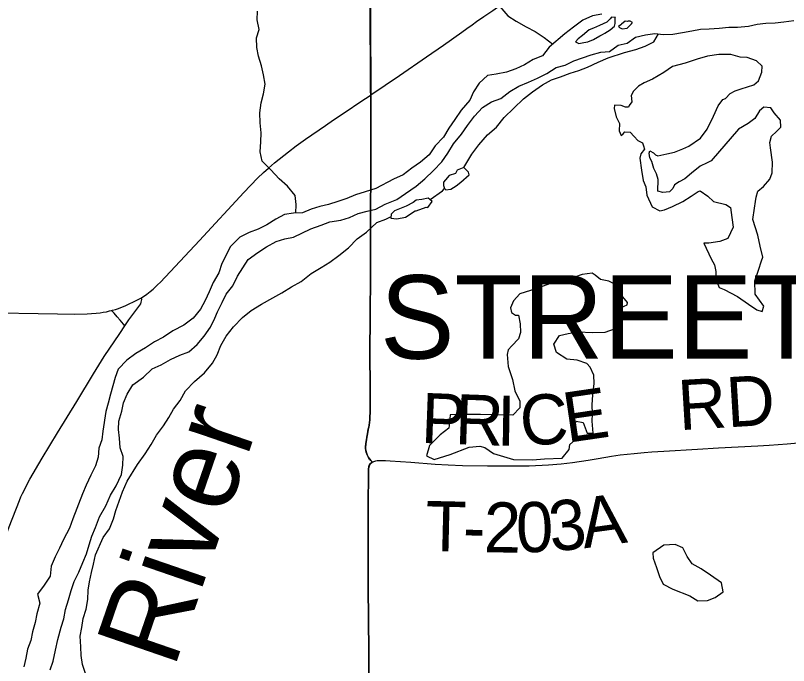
# Model space of a CAD drawing. Extents: x 0 to 34, y 0 to 22.
# Drawn here: x 4.634 to 5.511, y 19.311 to 20.048 of the extents above; entities that cross this region are included whole.
import ezdxf

# ---------------------------------------------------------------- set-up
doc = ezdxf.new("R2010")
doc.units = 0
for name, color, linetype in [('GM_X_Corporation', 7, 'Continuous'), ('GM_X_Corporation_Text', 7, 'Continuous'), ('GM_X_County_Road', 7, 'Continuous'), ('GM_X_Major_River', 7, 'Continuous'), ('GM_X_Major_River_Text', 7, 'Continuous'), ('GM_X_Minor_Lake', 7, 'Continuous'), ('GM_X_Minor_River', 7, 'Continuous'), ('GM_X_State_Route', 7, 'Continuous'), ('GM_X_Township_Road', 7, 'Continuous'), ('GM_X_Township_Road_Text', 7, 'Continuous')]:
    doc.layers.add(name, color=color, linetype=linetype)

msp = doc.modelspace()

# ---------------------------------------------------------------- linework, layer by layer
at = {"layer": 'GM_X_Corporation'}
for points in [[(5.03504, 19.29275), (5.03495, 19.3162), (5.0349, 19.32692), (5.03433, 19.39965), (5.03427, 19.41918), (5.03421, 19.43789), (5.03417, 19.48319), (5.03427, 19.50106), (5.03438, 19.52093), (5.03445, 19.52986), (5.03454, 19.5329), (5.03461, 19.5345), (5.03475, 19.53565), (5.03496, 19.53682), (5.03539, 19.53813), (5.0358, 19.539), (5.03614, 19.53952), (5.03672, 19.54018), (5.03742, 19.54089), (5.03811, 19.54154), (5.03872, 19.54193), (5.03731, 19.54354), (5.03559, 19.54551), (5.0347, 19.54673), (5.03384, 19.54824), (5.03316, 19.54973), (5.03268, 19.55096), (5.03187, 19.55339), (5.03142, 19.55502), (5.03126, 19.5567), (5.03122, 19.55786), (5.03129, 19.55916), (5.03155, 19.56216), (5.03187, 19.56508), (5.03212, 19.567), (5.03256, 19.56981), (5.0333, 19.57381), (5.03431, 19.57896), (5.03483, 19.5814), (5.03521, 19.5835), (5.03562, 19.58658), (5.03594, 19.58942), (5.03611, 19.59283), (5.03627, 19.5977), (5.03644, 19.6042), (5.03636, 19.61029), (5.03627, 19.63203), (5.03622, 19.65931), (5.03624, 19.67067), (5.03631, 19.70152), (5.03632, 19.71072), (5.03638, 19.71754), (5.03656, 19.72566), (5.03667, 19.73551), (5.03701, 19.95856), (5.037, 19.96155), (5.03541, 20.38763)], [(5.03504, 19.29275), (5.03495, 19.3162), (5.0349, 19.32692), (5.03433, 19.39965), (5.03427, 19.41918), (5.03421, 19.43789), (5.03417, 19.48319), (5.03427, 19.50106), (5.03438, 19.52093), (5.03445, 19.52986), (5.03454, 19.5329), (5.03461, 19.5345), (5.03475, 19.53565), (5.03496, 19.53682), (5.03539, 19.53813), (5.0358, 19.539), (5.03614, 19.53952), (5.03672, 19.54018), (5.03742, 19.54089), (5.03811, 19.54154), (5.03872, 19.54193), (5.03731, 19.54354), (5.03559, 19.54551), (5.0347, 19.54673), (5.03384, 19.54824), (5.03316, 19.54973), (5.03268, 19.55096), (5.03187, 19.55339), (5.03142, 19.55502), (5.03126, 19.5567), (5.03122, 19.55786), (5.03129, 19.55916), (5.03155, 19.56216), (5.03187, 19.56508), (5.03212, 19.567), (5.03256, 19.56981), (5.0333, 19.57381), (5.03431, 19.57896), (5.03483, 19.5814), (5.03521, 19.5835), (5.03562, 19.58658), (5.03594, 19.58942), (5.03611, 19.59283), (5.03627, 19.5977), (5.03644, 19.6042), (5.03636, 19.61029), (5.03627, 19.63203), (5.03622, 19.65931), (5.03624, 19.67067), (5.03631, 19.70152), (5.03632, 19.71072), (5.03638, 19.71754), (5.03656, 19.72566), (5.03667, 19.73551), (5.03701, 19.95856), (5.03541, 20.38763)], [(5.03541, 20.38763), (5.03701, 19.95856), (5.03667, 19.73551), (5.03656, 19.72566), (5.03638, 19.71754), (5.03632, 19.71072), (5.03631, 19.70152), (5.03624, 19.67067), (5.03622, 19.65931), (5.03627, 19.63203), (5.03636, 19.61029), (5.03644, 19.6042), (5.03627, 19.5977), (5.03611, 19.59283), (5.03594, 19.58942), (5.03562, 19.58658), (5.03521, 19.5835), (5.03483, 19.5814), (5.03431, 19.57896), (5.0333, 19.57381), (5.03256, 19.56981), (5.03212, 19.567), (5.03187, 19.56508), (5.03155, 19.56216), (5.03129, 19.55916), (5.03122, 19.55786), (5.03126, 19.5567), (5.03142, 19.55502), (5.03187, 19.55339), (5.03268, 19.55096), (5.03316, 19.54973), (5.03384, 19.54824), (5.0347, 19.54673), (5.03559, 19.54551), (5.03731, 19.54354), (5.03872, 19.54193), (5.03811, 19.54154), (5.03742, 19.54089), (5.03672, 19.54018), (5.03614, 19.53952), (5.0358, 19.539), (5.03539, 19.53813), (5.03496, 19.53682), (5.03475, 19.53565), (5.03461, 19.5345), (5.03454, 19.5329), (5.03445, 19.52986), (5.03438, 19.52093), (5.03427, 19.50106), (5.03417, 19.48319), (5.03421, 19.43789), (5.03427, 19.41918), (5.03433, 19.39965), (5.0349, 19.32692), (5.03495, 19.3162), (5.03504, 19.29275)]]:
    msp.add_lwpolyline(points, dxfattribs=at)
at = {"layer": 'GM_X_County_Road'}
for points in [[(5.03641, 19.95747), (5.03722, 19.958), (5.06951, 19.97999), (5.10031, 20.00105), (5.11964, 20.01458), (5.14046, 20.02928), (5.14603, 20.03323), (5.1521, 20.03756), (5.15714, 20.04119), (5.16532, 20.04683), (5.17552, 20.05393), (5.18625, 20.06136), (5.19565, 20.0675), (5.20101, 20.07071), (5.20416, 20.07242)], [(4.77733, 19.72791), (4.7831, 19.73211), (4.78704, 19.73509), (4.79035, 19.73784), (4.79531, 19.74249), (4.79877, 19.7458), (4.843, 19.79311), (4.89322, 19.84741), (4.90876, 19.86354), (4.91549, 19.87002), (4.92103, 19.87505), (4.92813, 19.88113), (4.94367, 19.89361), (4.95261, 19.90035), (4.96322, 19.90799), (4.98574, 19.92352), (4.99503, 19.92976), (5.00791, 19.93842), (5.02595, 19.95058), (5.03641, 19.95747)], [(4.7582, 19.69606), (4.76276, 19.70279), (4.77437, 19.71816), (4.77545, 19.71973), (4.77628, 19.7211), (4.77699, 19.72288), (4.77739, 19.72443), (4.77746, 19.72617), (4.77733, 19.72791)], [(4.7582, 19.69606), (4.75674, 19.69807), (4.75312, 19.70266), (4.74982, 19.70634), (4.74611, 19.71048), (4.74336, 19.71354)], [(4.48388, 19.06387), (4.4909, 19.08357), (4.50509, 19.12334), (4.51689, 19.1574), (4.52702, 19.18678), (4.54413, 19.23674), (4.57016, 19.31126), (4.58963, 19.36701), (4.60754, 19.41606), (4.61469, 19.43528), (4.62728, 19.46835), (4.63886, 19.498), (4.64054, 19.50225), (4.6422, 19.50595), (4.64442, 19.5103), (4.64642, 19.51425), (4.65072, 19.52223), (4.66445, 19.54621), (4.6819, 19.57492), (4.70396, 19.61022), (4.72287, 19.64163), (4.73488, 19.66126), (4.75248, 19.68762), (4.7582, 19.69606)]]:
    msp.add_lwpolyline(points, dxfattribs=at)
at = {"layer": 'GM_X_Major_River'}
for p, q in [((5.32778, 20.03355), (5.33266, 20.03851)), ((5.28958, 20.02072), (5.29674, 20.02494))]:
    msp.add_line(p, q, dxfattribs=at)
for points in [[(5.29889, 20.04963), (5.2883, 20.04766), (5.27737, 20.04264), (5.26683, 20.03497), (5.25705, 20.02731), (5.23938, 20.012), (5.23188, 20.00247), (5.22132, 19.99821), (5.21152, 19.99207), (5.20172, 19.98744), (5.19115, 19.98395), (5.17943, 19.98158), (5.16961, 19.97999), (5.15983, 19.97119), (5.15347, 19.96166), (5.14938, 19.95214), (5.13963, 19.94069), (5.13252, 19.93001), (5.12578, 19.92048), (5.11943, 19.91019), (5.11004, 19.90025), (5.10331, 19.88996), (5.09353, 19.88192), (5.08374, 19.87501), (5.07396, 19.86735), (5.06303, 19.86234), (5.04267, 19.85194), (5.03059, 19.84805), (5.01964, 19.84455), (5.00983, 19.84069), (4.99964, 19.83719), (4.98907, 19.8337), (4.97925, 19.83134), (4.96943, 19.82861), (4.95962, 19.82437), (4.9494, 19.82391), (4.9392, 19.82231), (4.9294, 19.8173), (4.91923, 19.81078), (4.90943, 19.80577), (4.89924, 19.8019), (4.88868, 19.79689), (4.87779, 19.7858), (4.87332, 19.77629), (4.86847, 19.76676), (4.86477, 19.75611), (4.85842, 19.74544), (4.85396, 19.73479), (4.8495, 19.72489), (4.84427, 19.71499), (4.83565, 19.70468), (4.82511, 19.69701), (4.81267, 19.69047), (4.80213, 19.68318), (4.79195, 19.67817), (4.78179, 19.67126), (4.77086, 19.66473), (4.7607, 19.65706), (4.75094, 19.64713), (4.74723, 19.63761), (4.74208, 19.61861), (4.73951, 19.60835), (4.73693, 19.59885), (4.73332, 19.57682), (4.73226, 19.56695), (4.72892, 19.55744), (4.72825, 19.54719), (4.72492, 19.5373), (4.7197, 19.52664), (4.71449, 19.5156), (4.7104, 19.50571), (4.69927, 19.47717), (4.69556, 19.4669), (4.68885, 19.45396), (4.68439, 19.44406), (4.67954, 19.43416), (4.6747, 19.4235), (4.67366, 19.41211), (4.66692, 19.4022)], [(5.18437, 19.95414), (5.19489, 19.96186), (5.20505, 19.96805), (5.21598, 19.97236), (5.22616, 19.97704), (5.2367, 19.98247), (5.24723, 19.98905), (5.25743, 19.99183), (5.26722, 19.9965), (5.28684, 20.00357), (5.29779, 20.00636), (5.30763, 20.00723), (5.31739, 20.01456), (5.3276, 20.01658), (5.33737, 20.02353), (5.3487, 20.02632), (5.35929, 20.02759), (5.36877, 20.02656), (5.37937, 20.02706), (5.39033, 20.02871), (5.40091, 20.03073), (5.41074, 20.03275), (5.42058, 20.03286), (5.43194, 20.03375), (5.44291, 20.03502), (5.45276, 20.03476), (5.46524, 20.03604), (5.47506, 20.03843), (5.4849, 20.03931), (5.4955, 20.03981), (5.50533, 20.04107), (5.51668, 20.04234)], [(5.29674, 20.02494), (5.29976, 20.02649), (5.30238, 20.02801), (5.30842, 20.03186), (5.31331, 20.03607), (5.31404, 20.03911), (5.31399, 20.04556), (5.31437, 20.04594), (5.30982, 20.04629), (5.30832, 20.04438), (5.30457, 20.04056), (5.29627, 20.0367), (5.28948, 20.03361), (5.28458, 20.03168), (5.27705, 20.02555), (5.27216, 20.02172), (5.26916, 20.01829), (5.27296, 20.01642), (5.27863, 20.0176), (5.28316, 20.01839), (5.28958, 20.02072)], [(5.33266, 20.03851), (5.33378, 20.04004), (5.33112, 20.04154), (5.32885, 20.04152), (5.32772, 20.04113), (5.32544, 20.04149), (5.3213, 20.03843), (5.32055, 20.03766), (5.31792, 20.03575), (5.31906, 20.03462), (5.3221, 20.03312), (5.32778, 20.03355)], [(4.96901, 19.80609), (4.98092, 19.8105), (4.99073, 19.81399), (5.00321, 19.81598), (5.01302, 19.81909), (5.02283, 19.82372), (5.03303, 19.82607), (5.04285, 19.82842), (5.0534, 19.83419), (5.06661, 19.83961), (5.0764, 19.84613), (5.08844, 19.85457), (5.09822, 19.86299), (5.10837, 19.87217), (5.11775, 19.88211), (5.12449, 19.89202), (5.13084, 19.90269), (5.13984, 19.91338), (5.14695, 19.92329), (5.15482, 19.93397), (5.16383, 19.94391), (5.174, 19.95005), (5.18437, 19.95414)], [(4.86019, 19.70481), (4.86327, 19.71186), (4.86883, 19.72256), (4.87327, 19.73211), (4.88073, 19.74169), (4.88592, 19.75239), (4.89225, 19.76196), (4.8982, 19.77152), (4.9091, 19.77924), (4.91887, 19.78582), (4.92979, 19.79164), (4.9396, 19.79479), (4.94943, 19.79681), (4.96901, 19.80609)], [(4.67377, 19.30613), (4.67706, 19.31604), (4.67958, 19.32823), (4.68247, 19.34041), (4.6861, 19.35451), (4.68902, 19.36404), (4.69118, 19.37431), (4.69447, 19.38537), (4.69738, 19.39604), (4.70105, 19.40633), (4.70624, 19.41665), (4.71066, 19.42771), (4.71471, 19.43763), (4.71801, 19.44793), (4.72093, 19.45746), (4.72498, 19.46738), (4.72977, 19.47959), (4.73683, 19.4922), (4.742, 19.50404), (4.74832, 19.51475), (4.75461, 19.52773), (4.75601, 19.538), (4.75628, 19.54788), (4.75314, 19.55772), (4.75226, 19.56872), (4.75101, 19.57858), (4.75166, 19.58808), (4.75494, 19.59951), (4.75673, 19.60903), (4.76079, 19.61857), (4.76749, 19.62928), (4.77951, 19.63778), (4.78925, 19.64739), (4.79943, 19.65207), (4.80996, 19.65789), (4.82051, 19.66295), (4.83069, 19.66686), (4.84045, 19.67496), (4.8483, 19.68454), (4.85538, 19.6945), (4.86019, 19.70481)], [(4.66692, 19.4022), (4.65943, 19.3919), (4.66216, 19.38168), (4.65847, 19.36951), (4.65665, 19.35964), (4.65371, 19.34899), (4.65189, 19.3395), (4.64818, 19.32961), (4.64599, 19.31935), (4.6438, 19.30947)]]:
    msp.add_lwpolyline(points, dxfattribs=at)
at = {"layer": 'GM_X_Minor_Lake'}
for p, q in [((5.45393, 19.91921), (5.42317, 19.88331)), ((5.13299, 19.86895), (5.12582, 19.86661)), ((5.08518, 19.83596), (5.07726, 19.83172)), ((5.28897, 19.61791), (5.29038, 19.63081)), ((5.37961, 19.39747), (5.39897, 19.39003))]:
    msp.add_line(p, q, dxfattribs=at)
for points in [[(5.42317, 19.88331), (5.41827, 19.881), (5.41035, 19.87715), (5.40058, 19.86911), (5.39305, 19.86298), (5.38665, 19.85952), (5.38137, 19.85606), (5.37951, 19.85188), (5.37576, 19.84805), (5.36819, 19.84724), (5.36251, 19.84871), (5.36278, 19.86199), (5.36084, 19.86842), (5.35814, 19.87447), (5.35581, 19.88242), (5.35351, 19.88657), (5.35271, 19.89188), (5.35345, 19.89454), (5.35763, 19.89229), (5.35992, 19.89004), (5.36257, 19.88892), (5.37278, 19.89127), (5.38146, 19.89324), (5.3909, 19.89672), (5.39769, 19.89981), (5.41087, 19.90901), (5.41836, 19.91931), (5.42581, 19.93378), (5.43102, 19.94558), (5.43626, 19.95283), (5.43928, 19.95399), (5.44454, 19.95972), (5.45019, 19.9628), (5.45699, 19.96475), (5.47134, 19.96941), (5.4766, 19.974), (5.48031, 19.98389), (5.48063, 19.99072), (5.47453, 19.99674), (5.46391, 20.00045), (5.45596, 20.00077), (5.44533, 20.00372), (5.43171, 20.004), (5.41886, 20.002), (5.40715, 19.9985), (5.39356, 19.99385), (5.3792, 19.99032), (5.36942, 19.98342), (5.35661, 19.97573), (5.34717, 19.97187), (5.34077, 19.96803), (5.33476, 19.96229), (5.33215, 19.95734), (5.33296, 19.95014), (5.32997, 19.94594), (5.32922, 19.94404), (5.32582, 19.94402), (5.32088, 19.94587), (5.31331, 19.94657), (5.31296, 19.94278), (5.3153, 19.93331), (5.31915, 19.92576), (5.31883, 19.91741), (5.32114, 19.91212), (5.3234, 19.91403), (5.32527, 19.91632), (5.33133, 19.91561), (5.33554, 19.91071), (5.33973, 19.90619), (5.34505, 19.90358), (5.34621, 19.90017), (5.34738, 19.89639), (5.34326, 19.89105), (5.34216, 19.88611), (5.34415, 19.87285), (5.34576, 19.8611), (5.34884, 19.85392), (5.35005, 19.84444), (5.35621, 19.83122), (5.36495, 19.82673), (5.37024, 19.82753), (5.37929, 19.83139), (5.39098, 19.83717), (5.4004, 19.84331), (5.4083, 19.84868), (5.41057, 19.84908), (5.41932, 19.84308), (5.4258, 19.83706), (5.43945, 19.83375), (5.44478, 19.83038), (5.44638, 19.81901), (5.44798, 19.80802), (5.44202, 19.79508), (5.43296, 19.79198), (5.42049, 19.78998), (5.41481, 19.78994), (5.4229, 19.77218)], [(5.4229, 19.77218), (5.42673, 19.76538), (5.4283, 19.7578), (5.42876, 19.74832), (5.43223, 19.73963), (5.43755, 19.73739), (5.45275, 19.72954), (5.4653, 19.72092), (5.47482, 19.71416), (5.48089, 19.71231), (5.48273, 19.7184), (5.47279, 19.73197), (5.47267, 19.74715), (5.47674, 19.75931), (5.48006, 19.76996), (5.48155, 19.77414), (5.47842, 19.78664), (5.47605, 19.79914), (5.47024, 19.81692), (5.47204, 19.82945), (5.47311, 19.83704), (5.47383, 19.84198), (5.47605, 19.84882), (5.48244, 19.85418), (5.48957, 19.86258), (5.49216, 19.86981), (5.49245, 19.88195), (5.49043, 19.89786), (5.48963, 19.90393), (5.49147, 19.91115), (5.4971, 19.9165), (5.50198, 19.92147), (5.50155, 19.92943), (5.49429, 19.93772), (5.49046, 19.94338), (5.48251, 19.94408), (5.47762, 19.93987), (5.47239, 19.93111), (5.46486, 19.92574), (5.45393, 19.91921)], [(5.12582, 19.86661), (5.12169, 19.86165), (5.11944, 19.85898), (5.11947, 19.85519), (5.12064, 19.85178), (5.12216, 19.85028), (5.12783, 19.85108), (5.13386, 19.85492), (5.13912, 19.85913), (5.14852, 19.86755), (5.14774, 19.87058), (5.14278, 19.87585), (5.13523, 19.87276), (5.13299, 19.86895)], [(5.07726, 19.83172), (5.06406, 19.82669), (5.0603, 19.82287), (5.05996, 19.81832), (5.06678, 19.81761), (5.0766, 19.81958), (5.08752, 19.82649), (5.08866, 19.8265), (5.09998, 19.83076), (5.10187, 19.8304), (5.10674, 19.83726), (5.10408, 19.83952), (5.10217, 19.84102), (5.09499, 19.83945), (5.08857, 19.83864), (5.08518, 19.83596)], [(5.29038, 19.63081), (5.28993, 19.64029), (5.2857, 19.64936), (5.28188, 19.65351), (5.27125, 19.65722), (5.25951, 19.65827), (5.24772, 19.66576), (5.24462, 19.67522), (5.25098, 19.68513), (5.2608, 19.68748), (5.27214, 19.68947), (5.28842, 19.68845), (5.3028, 19.68894), (5.3145, 19.69321), (5.31898, 19.70197), (5.32008, 19.70615), (5.32004, 19.71146), (5.32113, 19.71677), (5.32792, 19.71986), (5.32828, 19.72252), (5.32293, 19.72893), (5.31833, 19.73648), (5.31222, 19.74402), (5.3069, 19.74663), (5.29742, 19.74883), (5.29133, 19.75372), (5.2879, 19.75597), (5.27694, 19.75437), (5.26901, 19.75165), (5.2554, 19.74927), (5.24747, 19.74769), (5.23955, 19.74384), (5.22408, 19.73803), (5.20595, 19.73258), (5.19882, 19.72456), (5.19548, 19.71657), (5.19665, 19.71126), (5.20122, 19.70827), (5.20463, 19.70829), (5.20659, 19.69845), (5.20667, 19.68858), (5.20446, 19.68136), (5.19695, 19.67334), (5.19282, 19.66913), (5.19172, 19.66381), (5.19296, 19.65017), (5.19762, 19.63541), (5.20037, 19.62254), (5.20613, 19.61082), (5.20619, 19.60324), (5.19831, 19.59483), (5.18165, 19.59508), (5.16159, 19.59569), (5.14267, 19.59554), (5.12715, 19.59542), (5.12647, 19.58631), (5.12576, 19.58024), (5.11597, 19.57257), (5.10358, 19.56034), (5.10026, 19.54856), (5.109, 19.54445), (5.12712, 19.55028), (5.14863, 19.55841), (5.16073, 19.55965), (5.16642, 19.55817), (5.17631, 19.55142), (5.19908, 19.54477), (5.22027, 19.54417), (5.23389, 19.54542), (5.25394, 19.54595), (5.26219, 19.55587), (5.26291, 19.56157), (5.2693, 19.56731), (5.26694, 19.57829), (5.26989, 19.58818), (5.27785, 19.58672), (5.28249, 19.57462), (5.2893, 19.57429), (5.28806, 19.58793), (5.28837, 19.59628), (5.28792, 19.60652), (5.28897, 19.61791)], [(5.39897, 19.39003), (5.40772, 19.38441), (5.41869, 19.38487), (5.42737, 19.38797), (5.4364, 19.39449), (5.43481, 19.40472), (5.42225, 19.41335), (5.4116, 19.42047), (5.40134, 19.42608), (5.39559, 19.43476), (5.39098, 19.44459), (5.38224, 19.44832), (5.36938, 19.44746), (5.35696, 19.43864), (5.35738, 19.43257), (5.36087, 19.42198), (5.36436, 19.41177), (5.36859, 19.40307), (5.37961, 19.39747)]]:
    msp.add_lwpolyline(points, dxfattribs=at)
at = {"layer": 'GM_X_Minor_River'}
for points in [[(4.95203, 19.82403), (4.95273, 19.83379), (4.95152, 19.84403), (4.94273, 19.85458), (4.93321, 19.86285), (4.92367, 19.87302), (4.91413, 19.88281), (4.91178, 19.89341), (4.91245, 19.90479), (4.91275, 19.91504), (4.9119, 19.92641), (4.91144, 19.93779), (4.91286, 19.94918), (4.91543, 19.95944), (4.91724, 19.97007), (4.91565, 19.98068), (4.9133, 19.9909), (4.90981, 20.00187), (4.90784, 20.01172), (4.90775, 20.02272), (4.91071, 20.03223), (4.90835, 20.04321), (4.90865, 20.05307)], [(5.18339, 20.05823), (5.19255, 20.04768), (5.20206, 20.04168), (5.21346, 20.03532), (5.22334, 20.03009), (5.23362, 20.02296), (5.24338, 20.01547)], [(5.14278, 19.87585), (5.15175, 19.89071), (5.15962, 19.90139), (5.16937, 19.91285), (5.17952, 19.92127), (5.18852, 19.93234), (5.2103, 19.95375), (5.22047, 19.96141), (5.23176, 19.96947), (5.24193, 19.97523), (5.25213, 19.97835), (5.26307, 19.9826), (5.27289, 19.98571), (5.2827, 19.98958), (5.29477, 19.99498), (5.30608, 20), (5.32458, 20.00621), (5.33742, 20.00934), (5.34799, 20.01322), (5.35817, 20.01823), (5.36341, 20.02714)], [(5.10427, 19.83935), (5.1184, 19.84921), (5.12064, 19.85178)], [(4.71387, 19.30205), (4.71038, 19.31226), (4.70879, 19.32249), (4.70833, 19.33197), (4.70786, 19.3441), (4.70968, 19.35398), (4.71111, 19.36423), (4.71444, 19.37488), (4.71625, 19.38589), (4.71692, 19.39652), (4.71836, 19.40601), (4.72055, 19.41627), (4.72275, 19.42577), (4.72494, 19.43641), (4.73387, 19.4562), (4.74098, 19.46612), (4.74544, 19.47715), (4.74801, 19.48666), (4.75172, 19.49731), (4.7558, 19.50796), (4.761, 19.52014), (4.77259, 19.53881), (4.7812, 19.55102), (4.78831, 19.56169), (4.79428, 19.57236), (4.80215, 19.58266), (4.80813, 19.59219), (4.81336, 19.60172), (4.82123, 19.61164), (4.8272, 19.6223), (4.83734, 19.633), (4.84862, 19.64296), (4.85762, 19.65365), (4.86284, 19.66317), (4.8673, 19.67382), (4.87327, 19.68449), (4.88151, 19.69518), (4.89165, 19.7055), (4.90143, 19.71354), (4.91311, 19.72083), (4.92592, 19.72776), (4.93648, 19.73353), (4.9474, 19.74044), (4.95833, 19.7466), (4.96961, 19.75541), (4.98091, 19.76232), (4.99071, 19.76847), (5.00087, 19.77575), (5.01178, 19.78456), (5.02154, 19.79488), (5.03245, 19.80255), (5.0441, 19.81326), (5.05429, 19.81713), (5.06009, 19.82009)]]:
    msp.add_lwpolyline(points, dxfattribs=at)
at = {"layer": 'GM_X_State_Route'}
for points in [[(5.03641, 19.95747), (5.03722, 19.958), (5.06951, 19.97999), (5.10031, 20.00105), (5.11964, 20.01458), (5.14046, 20.02928), (5.14603, 20.03323), (5.1521, 20.03756), (5.15714, 20.04119), (5.16532, 20.04683), (5.17552, 20.05393), (5.18625, 20.06136), (5.19565, 20.0675), (5.20101, 20.07071), (5.20416, 20.07242)], [(4.77733, 19.72791), (4.7831, 19.73211), (4.78704, 19.73509), (4.79035, 19.73784), (4.79531, 19.74249), (4.79877, 19.7458), (4.843, 19.79311), (4.89322, 19.84741), (4.90876, 19.86354), (4.91549, 19.87002), (4.92103, 19.87505), (4.92813, 19.88113), (4.94367, 19.89361), (4.95261, 19.90035), (4.96322, 19.90799), (4.98574, 19.92352), (4.99503, 19.92976), (5.00791, 19.93842), (5.02595, 19.95058), (5.03641, 19.95747)], [(4.37591, 19.71325), (4.39404, 19.7131), (4.44874, 19.71258), (4.49034, 19.71207), (4.55556, 19.71167), (4.59342, 19.71126), (4.68214, 19.70976), (4.70139, 19.70957), (4.7157, 19.70982), (4.72047, 19.71012), (4.72567, 19.71043), (4.7302, 19.71103), (4.73374, 19.7115), (4.73742, 19.7122), (4.74111, 19.71301), (4.74336, 19.71354), (4.74445, 19.71381), (4.74784, 19.71474), (4.75107, 19.71567), (4.75386, 19.71677), (4.75674, 19.71804), (4.7595, 19.71922), (4.77186, 19.72514), (4.77733, 19.72791)]]:
    msp.add_lwpolyline(points, dxfattribs=at)
at = {"layer": 'GM_X_Township_Road'}
for points in [[(5.03892, 19.54138), (5.03752, 19.54299), (5.03579, 19.54495), (5.0349, 19.54618), (5.03404, 19.54769), (5.03337, 19.54918), (5.03289, 19.5504), (5.03207, 19.55283), (5.03163, 19.55447), (5.03146, 19.55615), (5.03143, 19.5573), (5.03149, 19.55861), (5.03175, 19.5616), (5.03207, 19.56452), (5.03232, 19.56645), (5.03276, 19.56926), (5.03351, 19.57326), (5.03452, 19.5784), (5.03504, 19.58085), (5.03541, 19.58295), (5.03582, 19.58603), (5.03614, 19.58887), (5.03631, 19.59228), (5.03647, 19.59715), (5.03664, 19.60364), (5.03656, 19.60973), (5.03648, 19.63148), (5.03644, 19.64966), (5.03642, 19.65876), (5.03645, 19.67012), (5.03651, 19.70096), (5.03653, 19.71017), (5.03658, 19.71699), (5.03677, 19.72511), (5.03688, 19.73496)], [(5.03892, 19.54138), (5.04062, 19.54223), (5.04191, 19.54274), (5.04304, 19.54308), (5.04427, 19.54331), (5.04569, 19.54344), (5.04727, 19.54348), (5.04863, 19.54349), (5.05374, 19.54333), (5.05915, 19.54313), (5.08267, 19.54154), (5.10994, 19.53942), (5.12483, 19.53844), (5.141, 19.53779), (5.1696, 19.53747), (5.20253, 19.53737), (5.21684, 19.53752), (5.2386, 19.53848), (5.25288, 19.53957), (5.26588, 19.541), (5.2837, 19.54381), (5.29473, 19.54564), (5.31001, 19.54819), (5.31981, 19.54971), (5.3358, 19.55156), (5.3469, 19.55255), (5.35557, 19.55319), (5.3692, 19.55405), (5.40765, 19.55642), (5.43122, 19.55784), (5.47588, 19.56015), (5.48892, 19.56091), (5.50912, 19.56224), (5.5215, 19.56348)], [(5.03525, 19.2922), (5.03515, 19.31564), (5.03511, 19.32637), (5.03453, 19.3991), (5.03448, 19.41863), (5.03441, 19.43733), (5.03437, 19.48264), (5.03448, 19.50051), (5.03458, 19.52038), (5.03465, 19.52931), (5.03475, 19.53235), (5.03481, 19.53394), (5.03495, 19.53509), (5.03517, 19.53626), (5.03559, 19.53757), (5.03601, 19.53844), (5.03635, 19.53896), (5.03693, 19.53962), (5.03763, 19.54034), (5.03832, 19.54098), (5.03892, 19.54138)]]:
    msp.add_lwpolyline(points, dxfattribs=at)

# ---------------------------------------------------------------- texts
at = {"layer": 'GM_X_Corporation_Text'}
msp.add_text('STREETSBORO', height=0.094697, rotation=0.00001, dxfattribs=at).set_placement((5.04756, 19.65888))
at = {"layer": 'GM_X_Major_River_Text'}
msp.add_text('River', height=0.094757, rotation=70.97519, dxfattribs=at).set_placement((4.81392, 19.30613))
at = {"layer": 'GM_X_Township_Road_Text'}
for s, height, rotation, p in [('RD', 0.056818, 3.4521, (5.38702, 19.57772)), ('E', 0.05682, 8.3339, (5.25962, 19.56341)), ('P', 0.05682, 357.85182, (5.09344, 19.56347)), ('R', 0.05682, 357.99249, (5.1319, 19.56203)), ('I', 0.05682, 359.01247, (5.17965, 19.56037)), ('C', 0.05682, 3.43958, (5.20777, 19.56007)), ('3', 0.05682, 5.29735, (5.24146, 19.44023)), ('A', 0.05682, 7.75245, (5.27895, 19.44376)), ('T', 0.05682, 358.61557, (5.09844, 19.44094)), ('2', 0.05682, 359.28328, (5.16497, 19.4394)), ('0', 0.05682, 1.65894, (5.20254, 19.43898)), ('-', 0.05682, 358.75174, (5.14107, 19.43991))]:
    msp.add_text(s, height=height, rotation=rotation, dxfattribs=at).set_placement(p)

doc.saveas('drawing.dxf')
